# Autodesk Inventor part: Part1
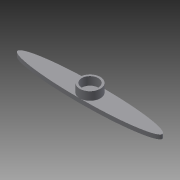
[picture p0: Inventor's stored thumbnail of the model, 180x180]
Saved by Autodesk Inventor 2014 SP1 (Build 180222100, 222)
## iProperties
Created: 2017-05
Part Number: Part1
Material: PVC-Piping
Document SubType Name: Modeling
Designer: L.Đ.P
Density: 1.4 g/cm^3
Appearance: Smooth - White
Author: L.Đ.P
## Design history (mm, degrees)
sketch "Sketch1" dims "d0" = 17.5
  geometry: L1 (0, 0)-(0, -2.5); 1 further point; 1 other entity
  constraints: 2 end point, 1 coincident, 1 vertical, 1 vertical alignment, 2 other
  dimensions: "d1" = 2.5 distance of L1.start L1.end
extrude "Extrusion1" new body sketch "Sketch1" stored distance "d2" = 1; taper "d3" = 0 deg
sketch "Sketch2"
  geometry: C1 r 3 at (0, 0); 1 further point; 1 other entity
  constraints: 1 centre point, 1 coincident, 1 other
  dimensions: "d4" = 6 diameter of C1
extrude "Extrusion2" join sketch "Sketch2" distance "d5" = 2; taper "d6" = 0 deg; dims "d23" = 1, "d24" = 0
sketch "Sketch3"
  geometry: C1 r 3 at (0, 0) reference; C2 r 2.5 at (0, 0)
  constraints: 1 centre point, 1 coincident
  dimensions: "d7" = 5 diameter of C2
extrude "Extrusion3" cut sketch "Sketch3" distance "d8" = 2; taper "d9" = 0 deg
sketch "Sketch4"
  geometry: C1 r 2 at (0, 0); 1 further point; 1 other entity
  constraints: 1 centre point, 1 coincident, 1 other
  dimensions: "d10" = 4 diameter of C1
extrude "Extrusion4" cut sketch "Sketch4" distance "d11" = 0.5; taper "d12" = 0 deg
sketch "Sketch5"
  geometry: C1 r 2 at (0, 0) reference; C2 r 1 at (0, 0)
  constraints: 1 centre point, 1 coincident
  dimensions: "d13" = 2 diameter of C2
extrude "Extrusion5" cut sketch "Sketch5" stored distance "d14" = 1; taper "d15" = 0 deg
sketch "Sketch6"
  geometry: L1 (0, 0)-(0, -1.269); L2 (0, 0)-(-1.481, 0); C1 r 0.5 at (-16, 0); 1 other entity
  constraints: 4 end point, 1 centre point, 1 perpendicular, 1 point on line, 1 vertical, 1 other
  dimensions: "d16" = 1 diameter of C1; "d17" = 16 distance of L1.start C1.centre
extrude "Extrusion6" cut sketch "Sketch6" stored distance "d18" = 1; taper "d19" = 0 deg
pattern_linear "Rectangular Pattern1" dims "d22" = 2.5
mirror "Mirror2"
body "Solid1"
